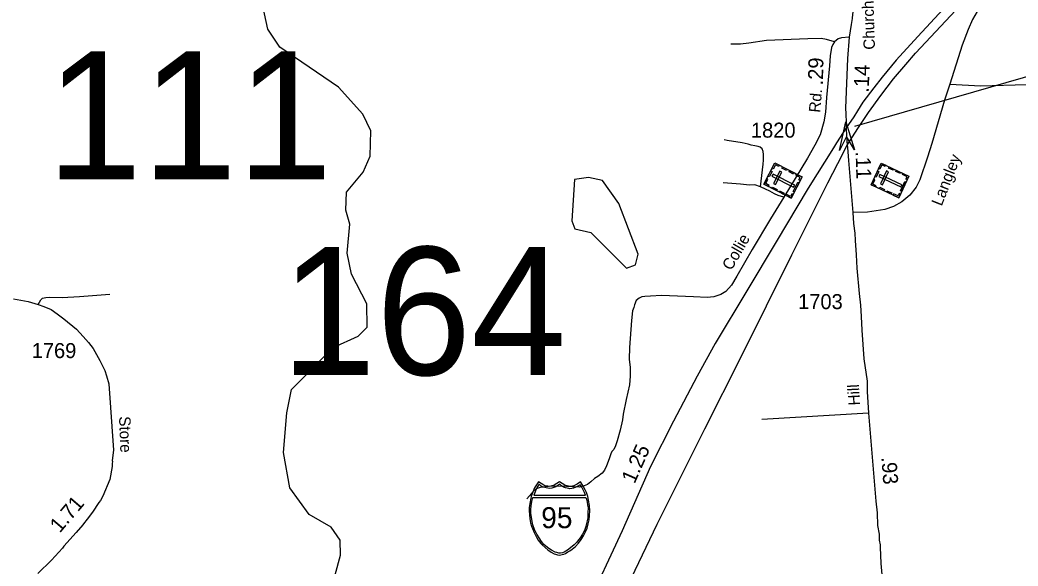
# Model space of a CAD drawing. Extents: x 2220236 to 2384410, y 720751 to 894131.
# Drawn here: x 2314254 to 2322567, y 787885 to 792436 of the extents above; entities that cross this region are included whole.
import ezdxf

# ---------------------------------------------------------------- set-up
doc = ezdxf.new("R2010")
doc.units = 0
for name, color, linetype in [('Exist Cultural Cemetery CELL', 7, 'Continuous'), ('Exist Hydrographic Creek Single Shore', 7, 'Continuous'), ('Exist Hydrographic Pond Under 1500 Sq Ft', 7, 'Continuous'), ('Exist Road Non-System Type 51', 7, 'Continuous'), ('Exist Road Primary Interstate Divided Center Attributed', 7, 'Continuous'), ('Exist Road Primary Interstate Mileage Hundredths English Label', 7, 'Continuous'), ('Exist Road Primary Interstate Shield CELL', 7, 'Continuous'), ('Exist Road Primary Interstate Shield Number Label', 7, 'Continuous'), ('Exist Road Primary US Service Attributed', 7, 'Continuous'), ('Exist Road Secondary Mileage Hundredths English Label', 7, 'Continuous'), ('Exist Road Secondary Structure Standard Bridge Attributed CELL', 7, 'Continuous'), ('Exist Road Secondary Structure Standard Bridge Number Label', 7, 'Continuous'), ('Exist Road Secondary Type 51 Attributed', 7, 'Continuous'), ('Exist Road Secondary Type 51 Label', 7, 'Continuous'), ('Exist Road Secondary Type 51 Number Label', 7, 'Continuous')]:
    doc.layers.add(name, color=color, linetype=linetype)

msp = doc.modelspace()

# ---------------------------------------------------------------- linework, layer by layer
at = {"layer": 'Exist Cultural Cemetery CELL'}
for points in [[(2320450.3, 791066.9), (2320541, 791244.1), (2320767.7, 791128), (2320677, 790950.8)], [(2320484.1, 791132.8), (2320507.7, 791178.9), (2320517.8, 791173.7), (2320494.2, 791127.6)], [(2320579.7, 791224.4), (2320574.5, 791214.3), (2320545.8, 791228.9), (2320527.4, 791192.8), (2320517.5, 791197.9), (2320541.1, 791244.1)], [(2320529.5, 791072.2), (2320546.1, 791063.6), (2320599.8, 791168.5), (2320583.1, 791177)], [(2320639.5, 791180.9), (2320601, 791200.6), (2320606.1, 791210.8), (2320644.7, 791191)], [(2320698.2, 791150.8), (2320659.6, 791170.6), (2320664.8, 791180.7), (2320703.4, 791161)], [(2321342.7, 791062.5), (2321427.1, 791242.8), (2321657.7, 791134.9), (2321573.4, 790954.6)], [(2321374.1, 791129.6), (2321396.1, 791176.5), (2321406.4, 791171.7), (2321384.4, 791124.7)], [(2321466.4, 791224.5), (2321461.6, 791214.2), (2321432.4, 791227.9), (2321415.2, 791191.1), (2321405.1, 791195.8), (2321427.1, 791242.9)], [(2321421.6, 791070.6), (2321438.6, 791062.7), (2321488.4, 791169.4), (2321471.5, 791177.3)], [(2321527.7, 791183.2), (2321488.5, 791201.6), (2321493.3, 791211.9), (2321532.5, 791193.5)], [(2321587.4, 791155.3), (2321548.2, 791173.6), (2321553, 791183.9), (2321592.2, 791165.6)], [(2320488.9, 791047.1), (2320494, 791057.2), (2320465.4, 791071.9), (2320483.9, 791108), (2320474, 791113), (2320450.3, 791066.9)], [(2320526.1, 791150.5), (2320517.6, 791133.9), (2320698.1, 791041.5), (2320706.6, 791058.1)], [(2320752.6, 791098.5), (2320742.4, 791103.8), (2320752.4, 791123.3), (2320716.4, 791141.8), (2320721.5, 791151.7), (2320767.7, 791128)], [(2321381.9, 791044.1), (2321386.7, 791054.4), (2321357.6, 791068.1), (2321374.8, 791104.8), (2321364.7, 791109.5), (2321342.7, 791062.5)], [(2321415.4, 791148.8), (2321407.5, 791131.9), (2321591.2, 791046), (2321599.1, 791062.9)], [(2321587.3, 791011.5), (2321623.2, 791088.4), (2321633.6, 791083.5), (2321597.6, 791006.7)], [(2321643.7, 791104.9), (2321633.3, 791109.8), (2321642.6, 791129.7), (2321606, 791146.8), (2321610.7, 791156.9), (2321657.7, 791134.9)], [(2320554.9, 791013.3), (2320516.3, 791033), (2320521.5, 791043.2), (2320560, 791023.4)], [(2320614.7, 790982.6), (2320576.1, 791002.4), (2320581.3, 791012.5), (2320619.9, 790992.8)], [(2320692.9, 791007.2), (2320731.6, 791082.7), (2320741.7, 791077.5), (2320703.1, 791002)], [(2321449.1, 791012.7), (2321409.9, 791031), (2321414.7, 791041.4), (2321453.9, 791023)], [(2321510, 790984.2), (2321470.7, 791002.6), (2321475.6, 791012.9), (2321514.8, 790994.5)], [(2320692, 790980.3), (2320681.8, 790985.5), (2320671.7, 790965.9), (2320635.8, 790984.3), (2320630.7, 790974.4), (2320676.9, 790950.8)], [(2321587.3, 790984.6), (2321576.9, 790989.5), (2321567.6, 790969.5), (2321531, 790986.6), (2321526.3, 790976.6), (2321573.3, 790954.6)]]:
    msp.add_lwpolyline(points, close=True, dxfattribs=at)
at = {"layer": 'Exist Hydrographic Creek Single Shore'}
msp.add_lwpolyline([(2316826.7, 787618.5), (2316922.7, 787976.9), (2316921.7, 788101.5), (2316845.8, 788210), (2316661.7, 788314.1), (2316500.7, 788537.3), (2316447.8, 788830.4), (2316477.7, 789163.1), (2316516.7, 789355.1), (2316862.6, 789707.3), (2317070.7, 789801.1), (2317144.8, 789876.3), (2317142.7, 790069.8), (2317014.8, 790317.4), (2316979.7, 790493.1), (2317001.6, 790733.6), (2316967.8, 790850.4), (2316973.7, 791001.5), (2317113.8, 791168.1), (2317170.8, 791301.7), (2317176.8, 791512), (2317108.7, 791650.3), (2316906.7, 791875.1), (2316419.7, 792209.7), (2316317.8, 792359.8), (2316221.6, 792808.7)], dxfattribs=at)
at = {"layer": 'Exist Hydrographic Pond Under 1500 Sq Ft'}
msp.add_lwpolyline([(2319304.8, 790368.1), (2319379.9, 790394.2), (2319403.9, 790483.7), (2319240.8, 790907.1), (2319105.7, 791098.4), (2318988.8, 791123.2), (2318871.7, 791105.3), (2318850.8, 790763.1), (2318876.7, 790695.3), (2319009.7, 790664.6), (2319304.8, 790368.1)], dxfattribs=at)
at = {"layer": 'Exist Road Non-System Type 51'}
msp.add_line((2321320.2, 789157.8), (2320434.4, 789106.3), dxfattribs=at)
for points in [[(2321037.2, 792253.7), (2320972.7, 792271.8), (2320927.1, 792280.6), (2320815.4, 792279.1), (2320472.7, 792264.4), (2320324.2, 792242.4), (2320256.6, 792235), (2320175.7, 792235)], [(2321998.1, 791901.2), (2322256.4, 791885.7), (2322637.7, 791896.7), (2322676.6, 791896.7), (2322701.2, 791890.2), (2322721.9, 791879.8), (2322745.2, 791861.7), (2322754.3, 791837.1), (2322756.9, 791773.6), (2322756.7, 791608.1)], [(2320422, 791045.5), (2320444.1, 791235.3), (2320446.3, 791268.4), (2320446.3, 791314.7), (2320444.1, 791339), (2320435.2, 791361.1), (2320419.8, 791376.6), (2320402.2, 791380.9), (2320373.5, 791387.5), (2320344.8, 791392), (2320318.3, 791400.8), (2320269.9, 791411.5), (2320145.7, 791430.1), (2320119.7, 791435.8)], [(2320422, 791045.5), (2320374, 791060.4), (2320331.7, 791060.3), (2320256.6, 791067.5), (2320111, 791078.6)], [(2320616.1, 790959.4), (2320569.8, 790972.6), (2320538.9, 790985.9), (2320499.2, 791007.9), (2320463.4, 791025.9), (2320422, 791045.5)], [(2320616.1, 790959.4), (2320505.8, 790778.4), (2320353.6, 790522.4), (2320225.7, 790299.5), (2320179.4, 790224.5), (2320133.1, 790173.7), (2320091.1, 790147.2), (2320033.8, 790127.4), (2319976.4, 790123), (2319865.1, 790129.6), (2319596, 790140.6), (2319505.5, 790134), (2319459.2, 790131.8), (2319432.7, 790127.4), (2319410.7, 790116.3), (2319386.5, 790096.6), (2319372.9, 790062.5), (2319367, 790040.4), (2319355.5, 790010.4), (2319346.7, 789931), (2319331.3, 789705.9), (2319326.9, 789608.7), (2319336.1, 789539.6), (2319337.5, 789466), (2319330.2, 789393.9), (2319303.7, 789271.8), (2319278.7, 789151.2), (2319271.3, 789102.6), (2319252.2, 789017.3), (2319227.2, 788927.5), (2319215.5, 788887.8), (2319200.8, 788855.4), (2319184.6, 788839.3), (2319175.8, 788818.7), (2319161.1, 788777.5), (2319140.5, 788720.1), (2319122.8, 788684.8), (2319102.2, 788659.8), (2319068.4, 788630.3), (2319040.5, 788615.6), (2319009.6, 788587.7), (2318981.7, 788564.1), (2318952.3, 788552.4), (2318911.1, 788542.1), (2318855.2, 788545), (2318805.2, 788547.9), (2318727.3, 788549.4), (2318655.2, 788546.5), (2318615.5, 788543.5), (2318586.1, 788539.1), (2318554.5, 788527.4), (2318525.1, 788502.3), (2318498.6, 788471.4), (2318475.1, 788446.4)], [(2314406.1, 790065.4), (2314426.7, 790103.1), (2314442, 790116.5), (2314468.5, 790122.1), (2314502.4, 790125.9), (2314604.4, 790124), (2314749.9, 790131.6), (2315002, 790149.4)]]:
    msp.add_lwpolyline(points, dxfattribs=at)
at = {"layer": 'Exist Road Primary Interstate Divided Center Attributed'}
for points in [[(2324771, 795862.6), (2324672.4, 795723), (2324529.7, 795470.8), (2324404.9, 795293.1), (2324260.7, 795096.5), (2324111, 794890.4), (2324043.6, 794804.3), (2323938.8, 794675.1), (2323805.9, 794521.5), (2323646.8, 794356.7), (2323377.2, 794066.4), (2323040.3, 793699.3), (2322778.2, 793416.5), (2322473.1, 793094.3), (2322160.5, 792761), (2321943.4, 792525), (2321731.9, 792298.4), (2321552.2, 792099.8), (2321436.1, 791959.4), (2321365, 791871.3), (2321275.1, 791749.6), (2321229.9, 791679), (2321198.4, 791629.7), (2321136.1, 791537.9)], [(2321144.7, 791392.4), (2321232.6, 791530.2), (2321321, 791665.3), (2321423.9, 791805.8), (2321528.8, 791944.4), (2321631.7, 792064.2), (2321712.2, 792159.8), (2322090.3, 792560.6), (2322515.2, 793013.8), (2322885.9, 793416.5), (2323170.4, 793723.6), (2323542.9, 794122.5), (2323810.6, 794409.1), (2323932.2, 794547.7), (2324061.4, 794699.4), (2324194.3, 794869.8), (2324321.6, 795032.8), (2324526.5, 795311.4), (2324639.5, 795479.3), (2324769.4, 795665.1)], [(2321136.1, 791537.9), (2321055.3, 791410.7), (2321029.9, 791370.7), (2320819.3, 791033.6), (2320552.5, 790586.9), (2320306.8, 790179.6), (2320045.7, 789738.5), (2319894.1, 789466), (2319697.6, 789092.4), (2319506.6, 788713.1), (2319270.8, 788179.3), (2318967.5, 787527.5), (2318793.5, 787120.2), (2318731.2, 786982.5), (2318658.7, 786822.4), (2318653.5, 786811.6)], [(2319011, 787125.2), (2319317.1, 787721.4), (2319561.4, 788232.7), (2319957.3, 789027.7), (2320260.5, 789628.9), (2320681.7, 790477.4), (2320983.5, 791078.6), (2321066.6, 791240.4), (2321144.7, 791392.4)]]:
    msp.add_lwpolyline(points, dxfattribs=at)
at = {"layer": 'Exist Road Primary Interstate Shield CELL'}
for points in [[(2318748.4, 787976.8), (2318757.9, 787977.7), (2318770.6, 787980.1), (2318783, 787984.2), (2318797.1, 787990.5), (2318818, 788002), (2318834.7, 788011.8), (2318854.1, 788024.8), (2318880.2, 788048.5), (2318906.2, 788075.9), (2318929.2, 788107), (2318947.5, 788136), (2318963.5, 788169.1), (2318977, 788200.1), (2318987.6, 788235.4), (2318994.7, 788269.6), (2318998.3, 788305.3), (2319000.6, 788344.9), (2318998, 788389.4), (2318990.2, 788435), (2318982.9, 788463.3), (2318971.9, 788497.3), (2318962.9, 788519), (2318942.1, 788557.4), (2318923.3, 788587), (2318896.1, 788567.8), (2318878.3, 788558.4), (2318867.5, 788553.5), (2318856.3, 788551.3), (2318835.8, 788548.9), (2318823, 788549.4), (2318811, 788552.1), (2318800.9, 788554.3), (2318792.6, 788558.4), (2318748.4, 788587), (2318704.1, 788558.4), (2318694.9, 788554.1), (2318685.3, 788552.1), (2318676.2, 788549.6), (2318661.1, 788548.9), (2318649.5, 788549.2), (2318637.6, 788551.3), (2318628.2, 788553.3), (2318617.7, 788558.4), (2318572.6, 788587), (2318554.9, 788561.3), (2318540.4, 788535.9), (2318525.1, 788499.9), (2318515.5, 788472.1), (2318508.7, 788449.2), (2318500.4, 788407.3), (2318496.1, 788370.7), (2318495.3, 788344.9), (2318500, 788280.4), (2318507.1, 788246), (2318514.3, 788218.2), (2318538.2, 788158.2), (2318556.1, 788124.6), (2318571.5, 788100.4), (2318593.1, 788073.2), (2318604.8, 788060.3), (2318649.6, 788021.1), (2318679.5, 788000.7), (2318703.4, 787987.8), (2318714.7, 787983.5), (2318732.2, 787978.6)], [(2318578, 788566.2), (2318567, 788549.3), (2318554.3, 788526.5), (2318544.2, 788502.8), (2318533.8, 788476.6), (2318965.4, 788476.5), (2318955.3, 788498.9), (2318944.6, 788521.4), (2318933.3, 788542), (2318919.6, 788561.9), (2318895.4, 788546.7), (2318877.8, 788538.3), (2318863.6, 788533.4), (2318851.6, 788530.7), (2318833, 788529.3), (2318824.7, 788529.8), (2318798.8, 788535.6), (2318781.2, 788542.8), (2318764.5, 788554), (2318751, 788566.7), (2318716.8, 788546), (2318701.6, 788539.3), (2318684.2, 788534.9), (2318665.1, 788532.5), (2318635.7, 788535.7), (2318612.6, 788543.6), (2318592.7, 788554)], [(2318967.9, 788455.2), (2318972.6, 788443), (2318978.9, 788416), (2318982.2, 788395.1), (2318985.7, 788371.1), (2318984.5, 788330), (2318982.5, 788287.4), (2318978.6, 788262.2), (2318973.3, 788239.3), (2318966.2, 788213.8), (2318954.7, 788180), (2318938.8, 788151.3), (2318918.9, 788119.5), (2318897.4, 788091.6), (2318888.1, 788080.1), (2318870.4, 788061.4), (2318838.1, 788035.5), (2318814.6, 788018), (2318786.4, 788001.3), (2318772.1, 787995), (2318755.5, 787991.5), (2318741.8, 787992.4), (2318725.1, 787996.8), (2318711.7, 788000.5), (2318682.3, 788016.4), (2318658.4, 788032.4), (2318618.6, 788065), (2318597.2, 788090.1), (2318577.1, 788119.5), (2318559.3, 788149.6), (2318540.2, 788189.3), (2318526.7, 788229.2), (2318516.9, 788272.2), (2318510.3, 788324.9), (2318509.6, 788356.9), (2318511.6, 788387.8), (2318514.5, 788403.9), (2318518.4, 788424), (2318526.3, 788455)]]:
    msp.add_lwpolyline(points, close=True, dxfattribs=at)
at = {"layer": 'Exist Road Primary US Service Attributed'}
msp.add_lwpolyline([(2321159.5, 792292.4), (2321097.7, 792286.5), (2321068.3, 792277.7), (2321037.2, 792253.7), (2321023.6, 792231.9), (2321012.4, 792206.6), (2321000.9, 792135.5), (2320996.2, 792054.2), (2320971.1, 791790.1), (2320962.2, 791668.2), (2320950.6, 791587), (2320918, 791479), (2320875.4, 791391.4), (2320813.9, 791283.1), (2320616.1, 790959.4)], dxfattribs=at)
at = {"layer": 'Exist Road Secondary Mileage Hundredths English Label'}
msp.add_line((2321207.3, 791549.3), (2322896.7, 792039.2), dxfattribs=at)
at = {"layer": 'Exist Road Secondary Structure Standard Bridge Attributed CELL'}
msp.add_lwpolyline([(2321080.2, 791349.2), (2321134, 791587), (2321206.3, 791354.2), (2321138.8, 791465.2)], close=True, dxfattribs=at)
at = {"layer": 'Exist Road Secondary Type 51 Attributed'}
for points in [[(2321174.2, 792929.5), (2321184.7, 792796.7), (2321187.1, 792752.8), (2321193.8, 792696.9), (2321197, 792579), (2321195.5, 792530.9), (2321187.9, 792483), (2321184.3, 792448.8), (2321176.8, 792396.9), (2321159.5, 792292.4)], [(2322613, 792905.6), (2322557.5, 792865.9), (2322482.4, 792814.1), (2322407.2, 792742.8), (2322341.2, 792668.9), (2322289.4, 792606.7), (2322245.4, 792540.7), (2322188.4, 792440.9), (2322152.1, 792356.7), (2322100.4, 792225.1), (2321998.1, 791901.2), (2321955.3, 791767.1), (2321849.3, 791407.2), (2321811.8, 791293.4), (2321749.4, 791103.4), (2321718.4, 791041.2), (2321665.9, 790977), (2321597.9, 790920.7), (2321529.9, 790881.8), (2321458.1, 790856.5), (2321312.4, 790835.1), (2321190, 790831.2)], [(2321159.5, 792292.4), (2321145.9, 792114.5), (2321131.3, 791700.6), (2321132.5, 791653.2), (2321134.4, 791582.6), (2321136.1, 791537.9)], [(2321136.1, 791537.9), (2321138.8, 791464.3), (2321144.7, 791392.4)], [(2321144.7, 791392.4), (2321146.3, 791372.8), (2321154.7, 791263.7), (2321190, 790831.2)], [(2321190, 790831.2), (2321197.8, 790739.9), (2321207.5, 790658.3), (2321209.4, 790598), (2321219.2, 790479.5), (2321223, 790366.7), (2321242.5, 790156.8), (2321254.1, 790059.6), (2321259.9, 789964.4), (2321265.8, 789849.7), (2321283.3, 789610.7), (2321310.7, 789425.6), (2321310.5, 789338.5), (2321320.2, 789157.8), (2321383.6, 788424.8), (2321392.6, 788327), (2321397.6, 788222.9), (2321410.4, 788149.2), (2321411.1, 788099.2), (2321417.4, 788061.3), (2321417.7, 788041.3), (2321425.1, 787906.1), (2321442.5, 787690.4)], [(2314200.2, 790112.7), (2314260.7, 790101.4), (2314323, 790090), (2314406.1, 790065.4), (2314451.5, 790048.4), (2314513.4, 790022.2), (2314563.2, 789985.9), (2314618, 789946.2), (2314725.5, 789860), (2314781.6, 789797.6), (2314825.2, 789747.7), (2314862.7, 789697.7), (2314918.8, 789597.9), (2314959.5, 789515.7), (2314973.8, 789470.5), (2314993.4, 789403), (2315034.1, 788851.5), (2315023.1, 788763.4), (2315023.6, 788756.5), (2315022, 788738.4), (2315022.5, 788715.6), (2315002.4, 788605.9), (2314944, 788467.5), (2314924.5, 788431.3), (2314910.5, 788415.1), (2314857.4, 788334.5), (2314814.2, 788276.1), (2314782.5, 788237.8), (2314776.7, 788227.8), (2314723.3, 788165.2), (2314620.5, 788050.1), (2314608.8, 788034), (2314517.9, 787933.1), (2314403.1, 787824)]]:
    msp.add_lwpolyline(points, dxfattribs=at)

# ---------------------------------------------------------------- texts
at = {"layer": 'Exist Road Primary Interstate Mileage Hundredths English Label'}
msp.add_text('1.25', height=125, rotation=66.16133, dxfattribs=at).set_placement((2319373, 788564.9))
at = {"layer": 'Exist Road Primary Interstate Shield Number Label'}
msp.add_text('95', height=175, dxfattribs=at).set_placement((2318595.5, 788200.5))
at = {"layer": 'Exist Road Secondary Mileage Hundredths English Label'}
for s, rotation, p in [('.29', 88.85086, (2320941.9, 791889.3)), ('.14', 87.98534, (2321323.4, 791828.4)), ('.11', 271.55574, (2321214.2, 791340.1)), ('.93', 274.34274, (2321428.2, 788792.2)), ('1.71', 49.5345, (2314585.7, 788155.2))]:
    msp.add_text(s, height=125, rotation=rotation, dxfattribs=at).set_placement(p)
at = {"layer": 'Exist Road Secondary Structure Standard Bridge Number Label'}
for s, p in [('111', (2314476.4, 791108.2)), ('164', (2316426.5, 789477.4))]:
    msp.add_text(s, height=1066.27, dxfattribs=at).set_placement(p)
at = {"layer": 'Exist Road Secondary Type 51 Label'}
for s, rotation, p in [('Church', 91.73894, (2321375.8, 792189.3)), ('Rd.', 84.59143, (2320918, 791660.6)), ('Langley', 68.54583, (2321930.6, 790879.2)), ('Collie', 59.99013, (2320178.7, 790341.9)), ('Hill', 92.99566, (2321250.8, 789225.5)), ('Store', 272.13531, (2315079.2, 789131.5))]:
    msp.add_text(s, height=95, rotation=rotation, dxfattribs=at).set_placement(p)
at = {"layer": 'Exist Road Secondary Type 51 Number Label'}
for s, p in [('1820', (2320342.1, 791455)), ('1703', (2320735.2, 790026.1)), ('1769', (2314351.6, 789617.9))]:
    msp.add_text(s, height=125, dxfattribs=at).set_placement(p)

doc.saveas('drawing.dxf')
